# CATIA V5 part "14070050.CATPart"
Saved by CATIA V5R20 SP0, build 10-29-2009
Part number: 14070050
Definition: NONE
Nomenclature: 14070050
Source: Unknown
Description: 14070050
Bounding box of the stored display mesh (mm): x -25 to 100, y -49 to 39.1, z -39.1 to 39.1
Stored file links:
  C:\Users\Utente\Desktop\IO LAVORO\3D X SITO CF\X SITO\PLASTICA\RF2\14070050.CATPart
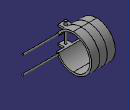
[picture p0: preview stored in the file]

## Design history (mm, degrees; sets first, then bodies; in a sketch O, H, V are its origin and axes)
Body1 "14070050" (main body)
  Solid1: solid without history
